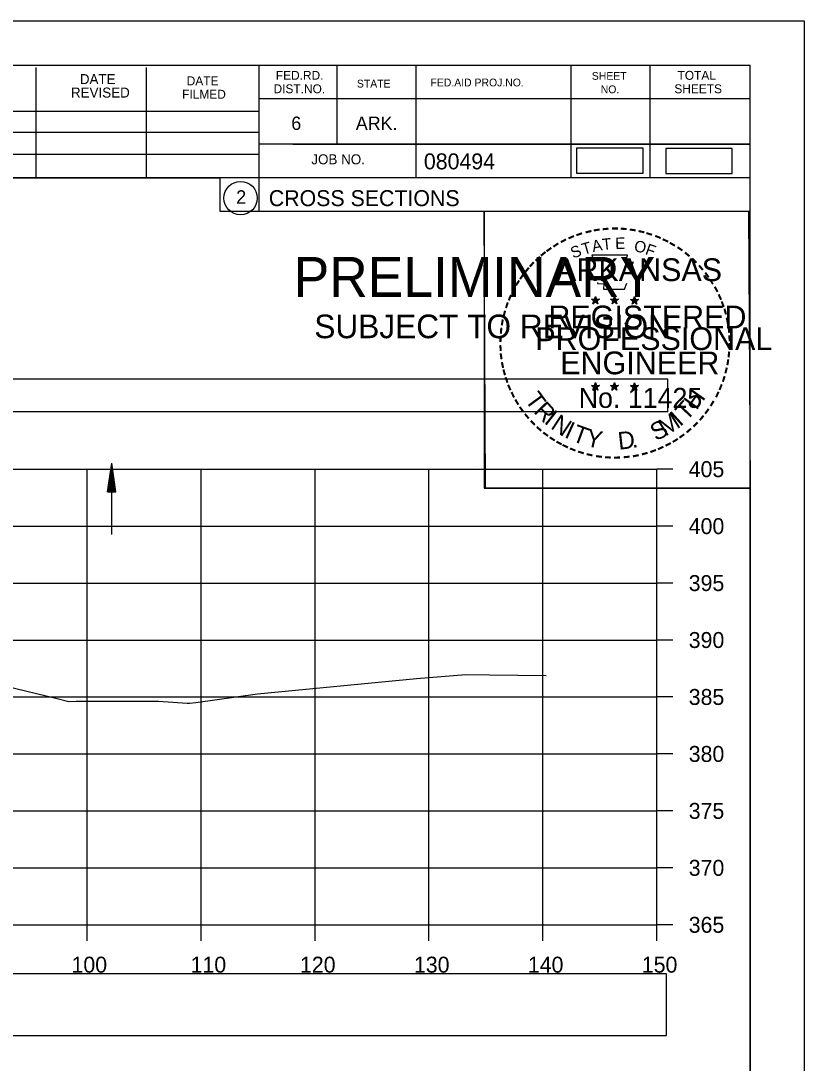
# Model space of a CAD drawing. Extents: x 1376273 to 1384221, y 378927 to 384592.
# Drawn here: x 1379851.5 to 1379920.3, y 381087 to 381178.5 of the extents above; entities that cross this region are included whole.
import ezdxf

# ---------------------------------------------------------------- set-up
doc = ezdxf.new("R2010")
doc.units = 0
for name, color, linetype in [('R_Axis', 7, 'Continuous'), ('R_Axis Annot', 7, 'Continuous'), ('R_Border', 7, 'Continuous'), ('R_Border PE', 7, 'Continuous'), ('R_Border Prem', 7, 'Continuous'), ('R_Drive', 7, 'Continuous'), ('R_Exist Surface', 7, 'Continuous'), ('R_Grid', 7, 'Continuous'), ('R_No Plot', 7, 'Continuous'), ('R_Water', 7, 'Continuous')]:
    doc.layers.add(name, color=color, linetype=linetype)

msp = doc.modelspace()

# ---------------------------------------------------------------- linework, layer by layer
at = {"layer": 'R_Axis'}
for p, q in [((1379907.327, 381099.17), (1379907.327, 381139.17)), ((1379908.727, 381139.17), (1379907.327, 381139.17)), ((1379908.727, 381134.17), (1379907.327, 381134.17)), ((1379908.727, 381129.17), (1379907.327, 381129.17)), ((1379908.727, 381124.17), (1379907.327, 381124.17)), ((1379908.727, 381119.17), (1379907.327, 381119.17)), ((1379908.727, 381114.17), (1379907.327, 381114.17)), ((1379908.727, 381109.17), (1379907.327, 381109.17)), ((1379908.727, 381104.17), (1379907.327, 381104.17)), ((1379607.327, 381099.17), (1379907.327, 381099.17)), ((1379857.327, 381097.77), (1379857.327, 381099.17)), ((1379867.327, 381097.77), (1379867.327, 381099.17)), ((1379877.327, 381097.77), (1379877.327, 381099.17)), ((1379887.327, 381097.77), (1379887.327, 381099.17)), ((1379897.327, 381097.77), (1379897.327, 381099.17)), ((1379907.327, 381097.77), (1379907.327, 381099.17)), ((1379908.727, 381099.17), (1379907.327, 381099.17))]:
    msp.add_line(p, q, dxfattribs=at)
at = {"layer": 'R_Axis Annot'}
for points in [[(1379606.489, 381144.243), (1379908.291, 381144.243), (1379908.291, 381147.06), (1379606.489, 381147.06)], [(1379606.494, 381089.461), (1379908.185, 381089.461), (1379908.185, 381094.872), (1379606.494, 381094.872)]]:
    msp.add_lwpolyline(points, close=True, dxfattribs=at)
at = {"layer": 'R_Border'}
for p, q in [((1379599.327, 381174.63), (1379915.507, 381174.63)), ((1379852.867, 381164.75), (1379852.867, 381174.43)), ((1379862.547, 381164.75), (1379862.547, 381174.43)), ((1379872.407, 381174.63), (1379872.407, 381161.83)), ((1379879.247, 381174.63), (1379879.247, 381167.69)), ((1379886.187, 381174.63), (1379886.187, 381164.75)), ((1379899.767, 381174.63), (1379899.767, 381164.75)), ((1379906.707, 381174.63), (1379906.707, 381164.75)), ((1379915.507, 380969.17), (1379915.507, 381174.63)), ((1379915.507, 381171.69), (1379872.407, 381171.69)), ((1379915.507, 381171.71), (1379915.507, 381171.71)), ((1379833.247, 381170.61), (1379872.407, 381170.61)), ((1379833.247, 381168.75), (1379872.407, 381168.75)), ((1379915.507, 381167.69), (1379872.407, 381167.69)), ((1379875.367, 381167.69), (1379915.507, 381167.69)), ((1379833.247, 381166.81), (1379872.407, 381166.81)), ((1379915.507, 381164.75), (1379833.247, 381164.75)), ((1379872.407, 381161.83), (1379915.507, 381161.83))]:
    msp.add_line(p, q, dxfattribs=at)
msp.add_circle((1379870.794, 381162.966), 1.467, dxfattribs=at)
at = {"layer": 'R_Border PE'}
for p, q in [((1379901.941, 381154.34), (1379901.9, 381154.088)), ((1379901.941, 381153.975), (1379901.941, 381154.34)), ((1379901.941, 381154.34), (1379901.99, 381154.09)), ((1379903.611, 381154.34), (1379903.57, 381154.088)), ((1379903.611, 381153.975), (1379903.611, 381154.34)), ((1379903.611, 381154.34), (1379903.66, 381154.09)), ((1379905.375, 381154.328), (1379905.334, 381154.076)), ((1379905.375, 381153.963), (1379905.375, 381154.328)), ((1379905.375, 381154.328), (1379905.424, 381154.078)), ((1379901.592, 381154.086), (1379901.941, 381153.975)), ((1379901.592, 381154.086), (1379901.845, 381154.041)), ((1379901.592, 381154.086), (1379901.829, 381153.964)), ((1379901.725, 381153.678), (1379901.941, 381153.975)), ((1379901.725, 381153.678), (1379901.851, 381153.922)), ((1379901.725, 381153.678), (1379901.939, 381153.895)), ((1379902.154, 381153.678), (1379901.939, 381153.892)), ((1379902.288, 381154.086), (1379901.941, 381153.975)), ((1379902.154, 381153.678), (1379901.941, 381153.975)), ((1379902.288, 381154.086), (1379902.002, 381154.037)), ((1379902.154, 381153.678), (1379902.017, 381153.969)), ((1379902.288, 381154.086), (1379902.084, 381153.984)), ((1379903.262, 381154.086), (1379903.611, 381153.975)), ((1379903.262, 381154.086), (1379903.515, 381154.041)), ((1379903.262, 381154.086), (1379903.499, 381153.964)), ((1379903.395, 381153.678), (1379903.611, 381153.975)), ((1379903.395, 381153.678), (1379903.521, 381153.922)), ((1379903.395, 381153.678), (1379903.609, 381153.895)), ((1379903.824, 381153.678), (1379903.609, 381153.892)), ((1379903.958, 381154.086), (1379903.611, 381153.975)), ((1379903.824, 381153.678), (1379903.611, 381153.975)), ((1379903.958, 381154.086), (1379903.672, 381154.037)), ((1379903.824, 381153.678), (1379903.687, 381153.969)), ((1379903.958, 381154.086), (1379903.754, 381153.984)), ((1379905.026, 381154.074), (1379905.375, 381153.963)), ((1379905.026, 381154.074), (1379905.279, 381154.029)), ((1379905.026, 381154.074), (1379905.263, 381153.952)), ((1379905.159, 381153.666), (1379905.375, 381153.963)), ((1379905.159, 381153.666), (1379905.285, 381153.91)), ((1379905.159, 381153.666), (1379905.373, 381153.883)), ((1379905.588, 381153.666), (1379905.373, 381153.88)), ((1379905.722, 381154.074), (1379905.375, 381153.963)), ((1379905.588, 381153.666), (1379905.375, 381153.963)), ((1379905.722, 381154.074), (1379905.436, 381154.025)), ((1379905.588, 381153.666), (1379905.451, 381153.957)), ((1379905.722, 381154.074), (1379905.518, 381153.972)), ((1379901.588, 381146.513), (1379901.937, 381146.402)), ((1379901.588, 381146.513), (1379901.841, 381146.468)), ((1379901.588, 381146.513), (1379901.825, 381146.391)), ((1379901.721, 381146.105), (1379901.937, 381146.402)), ((1379901.721, 381146.105), (1379901.847, 381146.349)), ((1379901.721, 381146.105), (1379901.935, 381146.322)), ((1379901.937, 381146.767), (1379901.896, 381146.515)), ((1379902.15, 381146.105), (1379901.935, 381146.319)), ((1379901.937, 381146.402), (1379901.937, 381146.767)), ((1379901.937, 381146.767), (1379901.986, 381146.517)), ((1379902.284, 381146.513), (1379901.937, 381146.402)), ((1379902.15, 381146.105), (1379901.937, 381146.402)), ((1379902.284, 381146.513), (1379901.998, 381146.464)), ((1379902.15, 381146.105), (1379902.013, 381146.396)), ((1379902.284, 381146.513), (1379902.08, 381146.411)), ((1379903.257, 381146.513), (1379903.606, 381146.402)), ((1379903.257, 381146.513), (1379903.51, 381146.468)), ((1379903.257, 381146.513), (1379903.494, 381146.391)), ((1379903.39, 381146.105), (1379903.606, 381146.402)), ((1379903.39, 381146.105), (1379903.516, 381146.349)), ((1379903.39, 381146.105), (1379903.604, 381146.322)), ((1379903.606, 381146.767), (1379903.565, 381146.515)), ((1379903.819, 381146.105), (1379903.604, 381146.319)), ((1379903.606, 381146.402), (1379903.606, 381146.767)), ((1379903.606, 381146.767), (1379903.655, 381146.517)), ((1379903.953, 381146.513), (1379903.606, 381146.402)), ((1379903.819, 381146.105), (1379903.606, 381146.402)), ((1379903.953, 381146.513), (1379903.667, 381146.464)), ((1379903.819, 381146.105), (1379903.682, 381146.396)), ((1379903.953, 381146.513), (1379903.749, 381146.411)), ((1379905.024, 381146.503), (1379905.373, 381146.392)), ((1379905.024, 381146.503), (1379905.277, 381146.458)), ((1379905.024, 381146.503), (1379905.261, 381146.381)), ((1379905.157, 381146.095), (1379905.373, 381146.392)), ((1379905.157, 381146.095), (1379905.283, 381146.339)), ((1379905.157, 381146.095), (1379905.371, 381146.312)), ((1379905.373, 381146.757), (1379905.332, 381146.505)), ((1379905.586, 381146.095), (1379905.371, 381146.309)), ((1379905.373, 381146.392), (1379905.373, 381146.757)), ((1379905.373, 381146.757), (1379905.422, 381146.507)), ((1379905.72, 381146.503), (1379905.373, 381146.392)), ((1379905.586, 381146.095), (1379905.373, 381146.392)), ((1379905.72, 381146.503), (1379905.434, 381146.454)), ((1379905.586, 381146.095), (1379905.449, 381146.386)), ((1379905.72, 381146.503), (1379905.516, 381146.401))]:
    msp.add_line(p, q, dxfattribs=at)
for points in [[(1379901.633, 381157.964), (1379901.902, 381157.137)], [(1379905.144, 381157.042), (1379905.286, 381157.326), (1379904.601, 381157.302), (1379904.749, 381157.964), (1379901.633, 381157.964)], [(1379902.125, 381155.541), (1379902.125, 381155.454), (1379902.688, 381155.435), (1379902.634, 381154.962), (1379904.504, 381154.962), (1379904.705, 381155.498)], [(1379901.941, 381154.34), (1379902.154, 381153.678), (1379901.592, 381154.086), (1379902.288, 381154.086), (1379901.725, 381153.678), (1379901.941, 381154.34)], [(1379903.611, 381154.34), (1379903.824, 381153.678), (1379903.262, 381154.086), (1379903.958, 381154.086), (1379903.395, 381153.678), (1379903.611, 381154.34)], [(1379905.375, 381154.328), (1379905.588, 381153.666), (1379905.026, 381154.074), (1379905.722, 381154.074), (1379905.159, 381153.666), (1379905.375, 381154.328)], [(1379901.937, 381146.767), (1379902.15, 381146.105), (1379901.588, 381146.513), (1379902.284, 381146.513), (1379901.721, 381146.105), (1379901.937, 381146.767)], [(1379903.606, 381146.767), (1379903.819, 381146.105), (1379903.257, 381146.513), (1379903.953, 381146.513), (1379903.39, 381146.105), (1379903.606, 381146.767)], [(1379905.373, 381146.757), (1379905.586, 381146.095), (1379905.024, 381146.503), (1379905.72, 381146.503), (1379905.157, 381146.095), (1379905.373, 381146.757)]]:
    msp.add_lwpolyline(points, dxfattribs=at)
for centre, radius in [((1379901.94, 381153.974), 0.172), ((1379903.61, 381153.974), 0.172), ((1379901.94, 381153.974), 0.145), ((1379901.94, 381153.974), 0.116), ((1379901.94, 381153.974), 0.0991), ((1379901.94, 381153.974), 0.0747), ((1379901.94, 381153.974), 0.0495), ((1379901.94, 381153.974), 0.0296), ((1379903.61, 381153.974), 0.145), ((1379903.61, 381153.974), 0.116), ((1379903.61, 381153.974), 0.0991), ((1379903.61, 381153.974), 0.0747), ((1379903.61, 381153.974), 0.0495), ((1379903.61, 381153.974), 0.0296), ((1379905.374, 381153.962), 0.172), ((1379905.374, 381153.962), 0.145), ((1379905.374, 381153.962), 0.116), ((1379905.374, 381153.962), 0.0991), ((1379905.374, 381153.962), 0.0747), ((1379905.374, 381153.962), 0.0495), ((1379905.374, 381153.962), 0.0296), ((1379901.936, 381146.401), 0.172), ((1379901.936, 381146.401), 0.145), ((1379901.936, 381146.401), 0.116), ((1379901.936, 381146.401), 0.0991), ((1379901.936, 381146.401), 0.0747), ((1379901.936, 381146.401), 0.0495), ((1379901.936, 381146.401), 0.0296), ((1379903.605, 381146.401), 0.172), ((1379903.605, 381146.401), 0.145), ((1379903.605, 381146.401), 0.116), ((1379903.605, 381146.401), 0.0991), ((1379903.605, 381146.401), 0.0747), ((1379903.605, 381146.401), 0.0495), ((1379903.605, 381146.401), 0.0296), ((1379905.372, 381146.391), 0.172), ((1379905.372, 381146.391), 0.145), ((1379905.372, 381146.391), 0.116), ((1379905.372, 381146.391), 0.0991), ((1379905.372, 381146.391), 0.0747), ((1379905.372, 381146.391), 0.0495), ((1379905.372, 381146.391), 0.0296)]:
    msp.add_circle(centre, radius, dxfattribs=at)
at = {"layer": 'R_Drive'}
for points in [[(1379900.291, 381165.152), (1379906.124, 381165.152), (1379906.124, 381167.339), (1379900.291, 381167.339)], [(1379908.115, 381165.13), (1379913.948, 381165.13), (1379913.948, 381167.316), (1379908.115, 381167.316)]]:
    msp.add_lwpolyline(points, close=True, dxfattribs=at)
at = {"layer": 'R_Exist Surface'}
msp.add_lwpolyline([(1379850.232, 381120.128), (1379854.575, 381119.072), (1379855.72, 381118.783), (1379856.368, 381118.809), (1379859.803, 381118.808), (1379863.598, 381118.807), (1379866.095, 381118.63), (1379866.316, 381118.617), (1379866.881, 381118.691), (1379872.27, 381119.449), (1379886.238, 381120.806), (1379890.555, 381121.139), (1379892.649, 381121.124), (1379897.615, 381121.043)], dxfattribs=at)
at = {"layer": 'R_Grid'}
for p, q in [((1379607.327, 381139.17), (1379907.327, 381139.17)), ((1379857.327, 381099.17), (1379857.327, 381139.17)), ((1379867.327, 381099.17), (1379867.327, 381139.17)), ((1379877.327, 381099.17), (1379877.327, 381139.17)), ((1379887.327, 381099.17), (1379887.327, 381139.17)), ((1379897.327, 381099.17), (1379897.327, 381139.17)), ((1379907.327, 381099.17), (1379907.327, 381139.17)), ((1379607.327, 381134.17), (1379907.327, 381134.17)), ((1379607.327, 381129.17), (1379907.327, 381129.17)), ((1379607.327, 381124.17), (1379907.327, 381124.17)), ((1379607.327, 381119.17), (1379907.327, 381119.17)), ((1379607.327, 381114.17), (1379907.327, 381114.17)), ((1379607.327, 381109.17), (1379907.327, 381109.17)), ((1379607.327, 381104.17), (1379907.327, 381104.17)), ((1379607.327, 381099.17), (1379907.327, 381099.17))]:
    msp.add_line(p, q, dxfattribs=at)
at = {"layer": 'R_No Plot'}
for p, q in [((1379586.926, 381178.525), (1379920.26, 381178.525)), ((1379891.541, 381139.375), (1379891.541, 381139.375))]:
    msp.add_line(p, q, dxfattribs=at)
for points in [[(1379586.92, 381178.525), (1379920.26, 381178.525), (1379920.26, 380965.187), (1379586.92, 380965.187)], [(1379833.247, 381174.63), (1379833.247, 381164.75), (1379868.979, 381164.75), (1379868.979, 381161.83), (1379892.179, 381161.83), (1379892.179, 381137.498), (1379915.507, 381137.498), (1379915.507, 380969.17), (1379599.327, 380969.17), (1379599.327, 381174.63)], [(1379892.179, 381161.83), (1379915.386, 381161.83), (1379915.507, 381137.498), (1379892.299, 381137.498)]]:
    msp.add_lwpolyline(points, close=True, dxfattribs=at)
at = {"layer": 'R_Water'}
for p, q in [((1379859.106, 381137.19), (1379859.481, 381139.69)), ((1379859.481, 381133.44), (1379859.481, 381139.69)), ((1379859.856, 381137.19), (1379859.481, 381139.69)), ((1379859.168, 381137.19), (1379859.481, 381139.273)), ((1379859.232, 381137.19), (1379859.481, 381138.843)), ((1379859.793, 381137.19), (1379859.481, 381139.273)), ((1379859.73, 381137.19), (1379859.481, 381138.843)), ((1379859.295, 381137.19), (1379859.481, 381138.427)), ((1379859.36, 381137.19), (1379859.481, 381138.003)), ((1379859.667, 381137.19), (1379859.481, 381138.427)), ((1379859.603, 381137.19), (1379859.481, 381138.003)), ((1379859.106, 381137.19), (1379859.856, 381137.19)), ((1379859.422, 381137.19), (1379859.481, 381137.585)), ((1379859.54, 381137.19), (1379859.481, 381137.585))]:
    msp.add_line(p, q, dxfattribs=at)

# ---------------------------------------------------------------- texts
at = {"layer": 'R_Axis Annot'}
for s, p in [('405', (1379910.127, 381138.47)), ('400', (1379910.127, 381133.47)), ('395', (1379910.127, 381128.47)), ('390', (1379910.127, 381123.47)), ('385', (1379910.127, 381118.47)), ('380', (1379910.127, 381113.47)), ('375', (1379910.127, 381108.47)), ('370', (1379910.127, 381103.47)), ('365', (1379910.127, 381098.47)), ('100', (1379855.955, 381094.97)), ('110', (1379866.407, 381094.97)), ('120', (1379876.01, 381094.97)), ('130', (1379886.01, 381094.97)), ('140', (1379896.01, 381094.97)), ('150', (1379906.01, 381094.97))]:
    msp.add_text(s, height=1.4, dxfattribs=at).set_placement(p)
at = {"layer": 'R_Border'}
for s, height, p in [('DATE', 0.8792, (1379856.687, 381172.97)), ('DATE', 0.7819, (1379866.067, 381172.87)), ('FED.RD.', 0.7819, (1379873.887, 381173.35)), ('STATE', 0.684, (1379881.007, 381172.67)), ('FED.AID PROJ.NO.', 0.684, (1379887.467, 381172.77)), ('SHEET', 0.684, (1379901.627, 381173.35)), ('TOTAL', 0.7819, (1379909.147, 381173.35)), ('REVISED', 0.8792, (1379855.907, 381171.79)), ('FILMED', 0.7819, (1379865.667, 381171.69)), ('DIST.NO.', 0.7819, (1379873.687, 381172.17)), ('NO.', 0.684, (1379902.407, 381172.17)), ('SHEETS', 0.7819, (1379908.867, 381172.17)), ('6', 1.172, (1379875.247, 381168.95)), ('ARK.', 1.1723, (1379880.907, 381168.95)), ('JOB NO.', 0.8792, (1379877.007, 381165.93)), ('080494', 1.4, (1379886.883, 381165.49)), ('2', 1.172, (1379870.411, 381162.48)), ('CROSS SECTIONS', 1.4, (1379873.271, 381162.26))]:
    msp.add_text(s, height=height, rotation=360, dxfattribs=at).set_placement(p)
at = {"layer": 'R_Border PE'}
for s, height, rotation, p in [('-', 1.6, 24.30721, (1379899.747, 381158.822)), ('-', 1.6, 19.17608, (1379900.381, 381159.091)), ('-', 1.6, 13.63015, (1379901.131, 381159.332)), ('-', 1.6, 10.21935, (1379901.809, 381159.494)), ('-', 1.6, 5.89682, (1379902.538, 381159.604)), ('-', 1.6, 0.18623, (1379903.31, 381159.676)), ('-', 1.6, 357.74304, (1379904.033, 381159.663)), ('-', 1.6, 352.16172, (1379904.777, 381159.607)), ('-', 1.6, 347.20489, (1379905.496, 381159.493)), ('-', 1.6, 342.3362, (1379906.131, 381159.338)), ('-', 1.6, 337.85509, (1379906.866, 381159.115)), ('-', 1.6, 34.06357, (1379898.517, 381158.135)), ('-', 1.6, 28.79182, (1379899.114, 381158.505)), ('S', 1, 21.59401, (1379899.988, 381157.642)), ('T', 1, 16.4036, (1379900.902, 381157.973)), ('A', 1, 11.21318, (1379901.728, 381158.224)), ('T', 1, 6.02276, (1379902.577, 381158.39)), ('E', 1, 0.83234, (1379903.682, 381158.5)), ('O', 1, 350.4515, (1379905.286, 381158.29)), ('F', 1, 340.07066, (1379906.24, 381158.062)), ('-', 1.6, 334.12109, (1379907.497, 381158.844)), ('-', 1.6, 329.64089, (1379908.076, 381158.561)), ('-', 1.6, 325.86266, (1379908.719, 381158.2)), ('-', 1.6, 42.96224, (1379897.03, 381156.945)), ('-', 1.6, 38.95066, (1379897.463, 381157.362)), ('-', 1.6, 36.23174, (1379897.939, 381157.74)), ('-', 1.6, 320.52971, (1379909.329, 381157.774)), ('-', 1.6, 50.61417, (1379896.179, 381155.981)), ('-', 1.6, 48.42305, (1379896.582, 381156.467)), ('ARKANSAS', 2, 360, (1379898.486, 381155.676)), ('-', 1.6, 315.57859, (1379909.928, 381157.286)), ('-', 1.6, 309.87973, (1379910.497, 381156.736)), ('-', 1.6, 54.23247, (1379895.766, 381155.414)), ('-', 1.6, 306.65218, (1379911.022, 381156.134)), ('-', 1.6, 62.87135, (1379895.128, 381154.273)), ('-', 1.6, 58.07063, (1379895.441, 381154.887)), ('-', 1.4, 303.67529, (1379911.508, 381155.566)), ('-', 1.6, 299.66835, (1379911.827, 381154.959)), ('-', 1.6, 67.77427, (1379894.869, 381153.662)), ('-', 1.6, 294.66279, (1379912.151, 381154.347)), ('-', 1.6, 72.39447, (1379894.65, 381153.032)), ('REGISTERED', 2, 360, (1379897.808, 381151.527)), ('DWB', 0.01, 360, (1379901.928, 381153.969)), ('DWB', 0.01, 360, (1379903.598, 381153.969)), ('DWB', 0.01, 360, (1379905.362, 381153.958)), ('-', 1.6, 290.57283, (1379912.408, 381153.77)), ('-', 1.6, 285.12326, (1379912.642, 381153.19)), ('-', 1.6, 81.20126, (1379894.321, 381151.605)), ('-', 1.6, 75.46096, (1379894.453, 381152.318)), ('-', 1.6, 280.54934, (1379912.842, 381152.448)), ('-', 1.6, 85.18634, (1379894.245, 381150.914)), ('PROFESSIONAL', 2, 360, (1379896.66, 381149.623)), ('-', 1.6, 276.59616, (1379913.004, 381151.68)), ('-', 1.6, 89.06224, (1379894.22, 381150.213)), ('-', 1.6, 274.33011, (1379913.064, 381150.958)), ('-', 1.6, 94.19588, (1379894.255, 381149.488)), ('-', 1.6, 269.94067, (1379913.098, 381150.326)), ('-', 1.6, 98.94793, (1379894.327, 381148.821)), ('ENGINEER', 2, 360, (1379898.847, 381147.498)), ('-', 1.6, 260.99529, (1379913.008, 381149.006)), ('-', 1.6, 263.5172, (1379913.079, 381149.66)), ('-', 1.6, 101.71495, (1379894.462, 381148.088)), ('-', 1.6, 105.45785, (1379894.624, 381147.493)), ('-', 1.6, 255.7626, (1379912.898, 381148.328)), ('-', 1.6, 109.08742, (1379894.839, 381146.862)), ('-', 1.6, 252.86809, (1379912.717, 381147.608)), ('-', 1.6, 114.06432, (1379895.093, 381146.266)), ('-', 1.6, 115.72885, (1379895.398, 381145.648)), ('T', 1.54, 306.04056, (1379895.697, 381145.24)), ('No. 11425', 1.757, 360, (1379900.474, 381144.547)), ('DWB', 0.01, 360, (1379901.924, 381146.396)), ('DWB', 0.01, 360, (1379903.593, 381146.397)), ('DWB', 0.01, 360, (1379905.36, 381146.387)), ('H', 1.54, 54.60883, (1379910.817, 381144.275)), ('-', 1.6, 244.61971, (1379912.232, 381146.306)), ('-', 1.6, 247.88866, (1379912.494, 381146.935)), ('-', 1.6, 120.44712, (1379895.755, 381145.062)), ('R', 1.54, 314.00497, (1379896.459, 381144.192)), ('T', 1.54, 46.64442, (1379909.927, 381143.332)), ('-', 1.6, 239.07125, (1379911.838, 381145.554)), ('-', 1.6, 125.89344, (1379896.158, 381144.501)), ('-', 1.6, 130.71812, (1379896.62, 381143.949)), ('I', 1.54, 321.96938, (1379897.36, 381143.26)), ('M', 1.54, 32.65632, (1379908.081, 381142.007)), ('I', 1.54, 42.11359, (1379909.366, 381142.854)), ('-', 1.6, 233.84524, (1379911.436, 381144.901)), ('-', 1.6, 134.22381, (1379897.137, 381143.404)), ('N', 1.54, 326.50021, (1379897.927, 381142.788)), ('I', 1.54, 335.36034, (1379899.135, 381142.002)), ('S', 1.54, 26.9312, (1379907.243, 381141.601)), ('-', 1.6, 225.76533, (1379910.527, 381143.771)), ('-', 1.6, 231.25377, (1379911.006, 381144.335)), ('-', 1.6, 138.93382, (1379897.662, 381142.94)), ('-', 1.6, 144.64634, (1379898.218, 381142.534)), ('T', 1.54, 339.89117, (1379899.796, 381141.675)), ('Y', 1.54, 347.85558, (1379901.013, 381141.229)), ('D', 1.54, 6.39691, (1379903.998, 381140.871)), ('-', 1.6, 215.73633, (1379909.456, 381142.79)), ('-', 1.6, 221.08509, (1379910.005, 381143.262)), ('-', 1.6, 148.08978, (1379898.779, 381142.163)), ('-', 1.6, 151.57039, (1379899.358, 381141.838)), ('-', 1.6, 154.60019, (1379899.88, 381141.591)), ('-', 1.6, 207.35684, (1379908.364, 381142.057)), ('-', 1.6, 212.24909, (1379908.922, 381142.403)), ('-', 1.6, 158.56121, (1379900.504, 381141.337)), ('-', 1.6, 162.79826, (1379901.191, 381141.124)), ('-', 1.6, 167.55551, (1379901.906, 381140.96)), ('-', 1.6, 191.28576, (1379905.715, 381141.024)), ('.', 1.54, 13.76417, (1379905.19, 381140.998)), ('-', 1.6, 195.47429, (1379906.444, 381141.223)), ('-', 1.6, 200.71842, (1379907.121, 381141.465)), ('-', 1.6, 204.25161, (1379907.74, 381141.738)), ('-', 1.6, 173.11546, (1379902.678, 381140.85)), ('-', 1.6, 176.51827, (1379903.426, 381140.797)), ('-', 1.6, 181.59176, (1379904.17, 381140.816)), ('-', 1.6, 185.81666, (1379904.979, 381140.892))]:
    msp.add_text(s, height=height, rotation=rotation, dxfattribs=at).set_placement(p)
at = {"layer": 'R_Border Prem'}
for s, height, p in [('PRELIMINARY', 3.5, (1379875.458, 381154.294)), ('DWB', 0.01, (1379876.205, 381156.143)), ('SUBJECT TO REVISION', 2.07511, (1379877.267, 381150.665))]:
    msp.add_text(s, height=height, rotation=360, dxfattribs=at).set_placement(p)

doc.saveas('drawing.dxf')
